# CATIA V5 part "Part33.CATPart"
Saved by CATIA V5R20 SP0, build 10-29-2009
Part number: 9AE052430-4
Revision: ANY
Definition: UNKNOWN
Nomenclature: 9AE052430-4
Source: Unknown
Bounding box of the stored display mesh (mm): x -4.935 to 4.935, y -4.756 to 4.756, z -10 to 10
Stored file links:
  C:\Users\Utente\Desktop\IO LAVORO\3D X SITO CF\CUMSA\3D files AE\AE 062430\Part33.CATPart
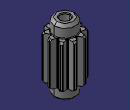
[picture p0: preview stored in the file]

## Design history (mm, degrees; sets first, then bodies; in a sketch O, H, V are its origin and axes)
Body1 "Cortar-Revolución1" (main body)
  Solid1: solid without history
